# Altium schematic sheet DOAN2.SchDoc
size A
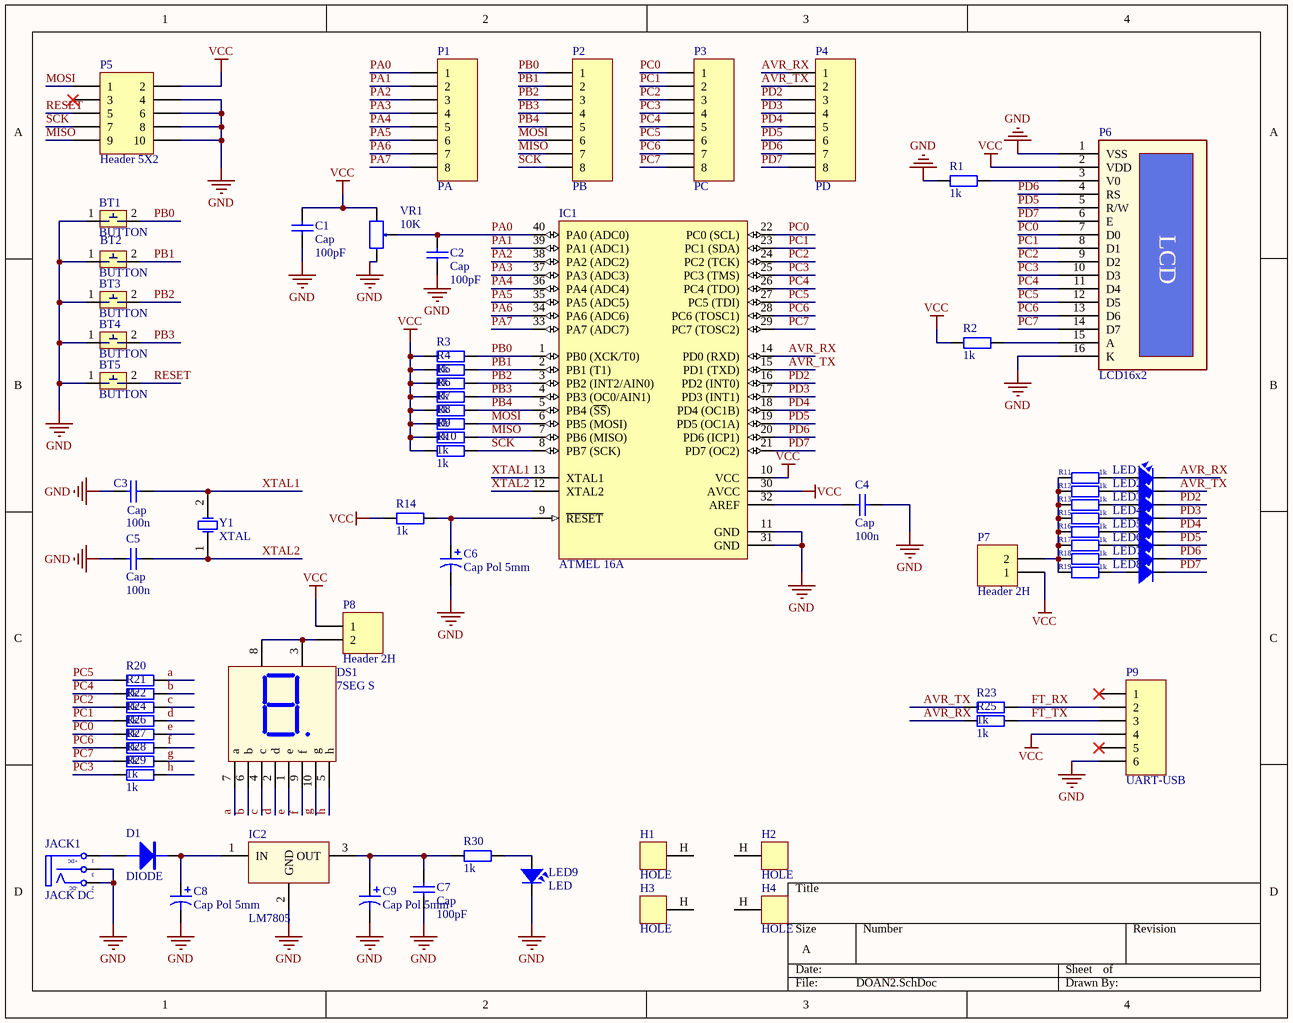
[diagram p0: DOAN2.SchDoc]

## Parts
BT1  BUTTON  [BUTTON 4 PIN]
BT2  BUTTON  [BUTTON 4 PIN]
BT3  BUTTON  [BUTTON 4 PIN]
BT4  BUTTON  [BUTTON 4 PIN]
BT5  BUTTON  [BUTTON 4 PIN]
C1  Cap  value 100pF  [CAP 10x DIP]
C2  Cap  value 100pF  [CAP 10x DIP]
C3  Cap  value 100n  [CAP 10x DIP]
C4  Cap  value 100n  [CAP 10x DIP]
C5  Cap  value 100n  [CAP 10x DIP]
C6  Cap Pol 5mm  [C5mm]
C7  Cap  value 100pF  [CAP 10x DIP]
C8  Cap Pol 5mm  [CAP_D10]
C9  Cap Pol 5mm  [CAP_D18]
D1  DIODE  [DIODE DIP]
DS1  7SEG S  [7SEGS]
H1  HOLE  [HOLE]
H2  HOLE  [HOLE]
H3  HOLE  [HOLE]
H4  HOLE  [HOLE]
IC1  ATMEL 16A  [DIP40/W0.6]
IC2  LM7805  [QTO-220]
JACK1  JACK DC  [JACK DC]
LED1  (no value)  [LED-5 GRe]
LED2  (no value)  [LED-5 GRe]
LED3  (no value)  [LED-5 GRe]
LED4  (no value)  [LED-5 GRe]
LED5  (no value)  [LED-5 GRe]
LED6  (no value)  [LED-5 GRe]
LED7  (no value)  [LED-5 GRe]
LED8  (no value)  [LED-5 GRe]
LED9  LED  [LED-5 GRe]
P1  PA  [HDR1X8]
P2  PB  [HDR1X8]
P3  PC  [HDR1X8]
P4  PD  [HDR1X8]
P5  Header 5X2  [IDC10 MALE]
P6  LCD16x2  [HDR1X16]
P7  Header 2H  [HDR1X2]
P8  Header 2H  [HDR1X2]
P9  UART-USB  [HDR1X6]
R1  1k  [R1/2W]
R2  1k  [R1/2W]
R3  1k  [R1/2W]
R4  1k  [R1/2W]
R5  1k  [R1/2W]
R6  1k  [R1/2W]
R7  1k  [R1/2W]
R8  1k  [R1/2W]
R9  1k  [R1/2W]
R10  1k  [R1/2W]
R11  1k  [R1/2W]
R12  1k  [R1/2W]
R13  1k  [R1/2W]
R14  1k  [R1/2W]
R15  1k  [R1/2W]
R16  1k  [R1/2W]
R17  1k  [R1/2W]
R18  1k  [R1/2W]
R19  1k  [R1/2W]
R20  1k  [R1/2W]
R21  1k  [R1/2W]
R22  1k  [R1/2W]
R23  1k  [R1/2W]
R24  1k  [R1/2W]
R25  1k  [R1/2W]
R26  1k  [R1/2W]
R27  1k  [R1/2W]
R28  1k  [R1/2W]
R29  1k  [R1/2W]
R30  1k  [R1/2W]
VR1  10K  [RVAR]
Y1  XTAL  [CRYSTAL DIP]

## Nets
GND: BT1.1 BT2.1 BT3.1 BT4.1 BT5.1 C1.1 C2.1 C3.1 C4.2 C5.1 C6.2 C7.1 C8.2 C9.2 IC1.11(GND) IC1.31(GND) IC2.2(GND) JACK1.2(TN) JACK1.3(S) LED9.2 P5.4 P5.6 P5.8 P5.10 P6.1(VSS) P6.16(K) P9.6 R1.2 VR1.3
VCC: C1.2 IC1.10(VCC) IC1.30(AVCC) P5.2 P6.2(VDD) P7.1 P8.1 P9.4 R2.2 R3.1 R4.1 R5.1 R6.1 R7.1 R8.1 R9.1 R10.1 R14.2 VR1.1
a: DS1.7(a) R20.2
AVR_RX: IC1.14(PD0_(RXD)) LED1.2 P4.1 R25.1
AVR_TX: IC1.15(PD1_(TXD)) LED2.2 P4.2 R23.1
b: DS1.6(b) R21.2
c: DS1.4(c) R22.2
d: DS1.2(d) R24.2
e: DS1.1(e) R26.2
f: DS1.9(f) R27.2
FT_RX: P9.2 R23.2
FT_TX: P9.3 R25.2
g: DS1.10(g) R28.2
h: DS1.5(h) R29.2
MISO: IC1.7(PB6_(MISO)) P2.7 P5.9 R9.2
MOSI: IC1.6(PB5_(MOSI)) P2.6 P5.1 R8.2
PA0: C2.2 IC1.40(PA0_(ADC0)) P1.1 VR1.2
PA1: IC1.39(PA1_(ADC1)) P1.2
PA2: IC1.38(PA2_(ADC2)) P1.3
PA3: IC1.37(PA3_(ADC3)) P1.4
PA4: IC1.36(PA4_(ADC4)) P1.5
PA5: IC1.35(PA5_(ADC5)) P1.6
PA6: IC1.34(PA6_(ADC6)) P1.7
PA7: IC1.33(PA7_(ADC7)) P1.8
PB0: BT1.2 IC1.1(PB0_(XCK/T0)) P2.1 R3.2
PB1: BT2.2 IC1.2(PB1_(T1)) P2.2 R4.2
PB2: BT3.2 IC1.3(PB2_(INT2/AIN0)) P2.3 R5.2
PB3: BT4.2 IC1.4(PB3_(OC0/AIN1)) P2.4 R6.2
PB4: IC1.5(PB4_(~{SS})) P2.5 R7.2
PC0: IC1.22(PC0_(SCL)) P3.1 P6.7(D0) R26.1
PC1: IC1.23(PC1_(SDA)) P3.2 P6.8(D1) R24.1
PC2: IC1.24(PC2_(TCK)) P3.3 P6.9(D2) R22.1
PC3: IC1.25(PC3_(TMS)) P3.4 P6.10(D3) R29.1
PC4: IC1.26(PC4_(TDO)) P3.5 P6.11(D4) R21.1
PC5: IC1.27(PC5_(TDI)) P3.6 P6.12(D5) R20.1
PC6: IC1.28(PC6_(TOSC1)) P3.7 P6.13(D6) R27.1
PC7: IC1.29(PC7_(TOSC2)) P3.8 P6.14(D7) R28.1
PD2: IC1.16(PD2_(INT0)) LED3.2 P4.3
PD3: IC1.17(PD3_(INT1)) LED4.2 P4.4
PD4: IC1.18(PD4_(OC1B)) LED5.2 P4.5
PD5: IC1.19(PD5_(OC1A)) LED6.2 P4.6 P6.5(R/W)
PD6: IC1.20(PD6_(ICP1)) LED7.2 P4.7 P6.4(RS)
PD7: IC1.21(PD7_(OC2)) LED8.2 P4.8 P6.6(E)
RESET: BT5.2 P5.5
SCK: IC1.8(PB7_(SCK)) P2.8 P5.7 R10.2
XTAL1: C3.2 IC1.13(XTAL1) Y1.2(OSC2)
XTAL2: C5.2 IC1.12(XTAL2) Y1.1(OSC1)
NetC4_1: C4.1 IC1.32(AREF)
NetC6_1: C6.1 IC1.9(~{RESET}) R14.1
NetC7_2: C7.2 C9.1 IC2.3(OUT) R30.1
NetC8_1: C8.1 D1.2 IC2.1(IN)
NetD1_1: D1.1 JACK1.1(T)
NetDS1_3: DS1.3(Vcc) DS1.8(Vcc) P8.2
NetLED1_1: LED1.1 R11.2
NetLED2_1: LED2.1 R12.2
NetLED3_1: LED3.1 R13.2
NetLED4_1: LED4.1 R15.2
NetLED5_1: LED5.1 R16.2
NetLED6_1: LED6.1 R17.2
NetLED7_1: LED7.1 R18.2
NetLED8_1: LED8.1 R19.2
NetLED9_1: LED9.1 R30.2
NetP6_3: P6.3(V0) R1.1
NetP6_15: P6.15(A) R2.1
NetP7_2: P7.2 R11.1 R12.1 R13.1 R15.1 R16.1 R17.1 R18.1 R19.1

Not connected (* = marked no-connect by the designer): H1 H(HOLE); H2 H(HOLE); H3 H(HOLE); H4 H(HOLE); P5 3*; P9 1* 5*

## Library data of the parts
C1-C5 C7 = Cap: Capacitor
C6 C8 C9 = Cap Pol 5mm: Polarized Capacitor (Axial)
DS1 = LED7S: Single 7 Seg Dipslay; Value: LED 7S SEG
IC1 = ATmega16A-PU: 8-Bit AVR Microcontroller with 16K Bytes of In-System Programmable Flash Memory; Value: Atmega 16L
IC2 = LM78xx: On ap +, from + 5 to + 24VDC
JACK1 = JACK DC: Value: Jac DC
LED1-LED9 = LED: LED Single colour Green and Red; Value: LED 3 ly Single Colour
P1-P4 = Header 8
P6 = LCD Text
P9 = Header 6
R1-R30 = RESISTOR: Value: R1/4W - 1K
VR1 = VAR RES: Value: VR 10K
Y1 = XTAL: Crystal Oscillator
